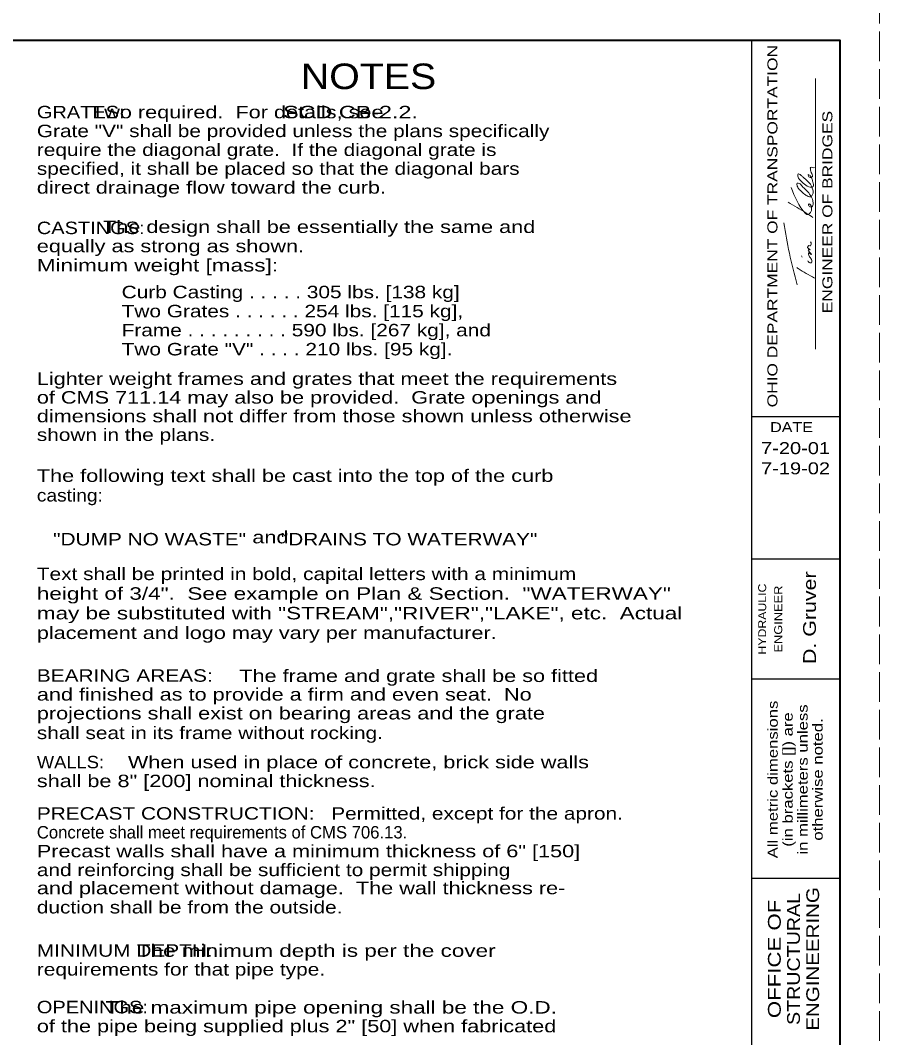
# Model space of a CAD drawing. Extents: x 1352.5 to 1386.5, y 735.9 to 779.9.
# Drawn here: x 1375.75 to 1386.51, y 744.93 to 757.67 of the extents above; entities that cross this region are included whole.
import ezdxf
from ezdxf.enums import TextEntityAlignment as Align

# ---------------------------------------------------------------- set-up
doc = ezdxf.new("R2010")
doc.units = 0
doc.header["$LTSCALE"] = 0.062
doc.linetypes.add('LONG_DASHED', pattern=[7.5, 6, -1.5])
doc.layers.add('1', color=7, linetype='Continuous', lineweight=13)

msp = doc.modelspace()

# ---------------------------------------------------------------- linework, layer by layer
at = {"layer": '1', "lineweight": 25}
for p, q in [((1354.513, 757.41967), (1386.013, 757.41967)), ((1384.913, 736.41967), (1384.913, 757.41967)), ((1386.013, 757.41967), (1386.013, 736.41967)), ((1386.013, 752.70383), (1384.913, 752.70383)), ((1386.013, 750.91967), (1384.913, 750.91967)), ((1386.013, 749.41967), (1384.913, 749.41967)), ((1386.013, 746.91967), (1384.913, 746.91967))]:
    msp.add_line(p, q, dxfattribs=at)
at = {"layer": '1'}
for p, q in [((1385.71175, 753.55067), (1385.71175, 756.94075)), ((1385.54425, 754.70158), (1385.53408, 754.72083))]:
    msp.add_line(p, q, dxfattribs=at)
at = {"layer": '1', "linetype": 'LONG_DASHED'}
msp.add_lwpolyline([(1352.513, 735.91967), (1386.513, 735.91967), (1386.513, 757.91967), (1352.513, 757.91967)], close=True, dxfattribs=at)
at = {"layer": '1', "lineweight": 40}
msp.add_lwpolyline([(1354.513, 757.41967), (1386.013, 757.41967), (1386.013, 736.41967), (1354.513, 736.41967)], close=True, dxfattribs=at)
msp.add_lwpolyline([(1354.513, 757.41967), (1386.013, 757.41967), (1386.013, 736.41967), (1354.513, 736.41967)], close=True, dxfattribs=at)
at = {"layer": '1'}
for points in [[(1385.40483, 755.57667), (1385.588, 755.24833), (1385.60317, 755.23775), (1385.61333, 755.23775), (1385.64525, 755.26142), (1385.66033, 755.29558), (1385.65533, 755.34683), (1385.63842, 755.36867), (1385.62492, 755.36867), (1385.62317, 755.35567), (1385.63333, 755.3405), (1385.64683, 755.33208), (1385.66192, 755.33208), (1385.67708, 755.35367), (1385.6805, 755.373), (1385.67025, 755.42833), (1385.588, 755.54875), (1385.5425, 755.59342), (1385.50558, 755.628), (1385.48042, 755.63017), (1385.48217, 755.59158), (1385.50733, 755.55283), (1385.57458, 755.4905), (1385.61667, 755.46508), (1385.65033, 755.46058), (1385.67367, 755.48658), (1385.6805, 755.52075), (1385.67542, 755.5465), (1385.64525, 755.61967), (1385.615, 755.65167), (1385.55442, 755.70508), (1385.52575, 755.73092), (1385.49225, 755.74617), (1385.48883, 755.71817), (1385.49892, 755.69233), (1385.55608, 755.63242), (1385.62675, 755.58517), (1385.67875, 755.5875), (1385.67708, 755.64517), (1385.66525, 755.68808), (1385.65192, 755.71383), (1385.64175, 755.72458), (1385.61833, 755.73958), (1385.62008, 755.7225), (1385.65533, 755.701), (1385.67025, 755.71175), (1385.65717, 755.76542), (1385.64858, 755.79333), (1385.64525, 755.806), (1385.64525, 755.81883), (1385.64525, 755.8275), (1385.67025, 755.82533), (1385.69567, 755.82533)], [(1385.366, 755.39442), (1385.58975, 755.25692), (1385.67542, 755.20125)], [(1385.48225, 754.35742), (1385.38358, 754.75267), (1385.31233, 755.135)], [(1385.61333, 754.65633), (1385.62158, 754.64567), (1385.65875, 754.63275), (1385.6635, 754.66517), (1385.63842, 754.70158), (1385.62317, 754.73783), (1385.62317, 754.75708), (1385.63842, 754.75083), (1385.64858, 754.74), (1385.65875, 754.73567), (1385.63508, 754.76783), (1385.62317, 754.78283), (1385.62008, 754.80017), (1385.6435, 754.79358), (1385.63508, 754.80225), (1385.60992, 754.83008), (1385.62008, 754.84525), (1385.63683, 754.84725), (1385.64525, 754.84525), (1385.65533, 754.86658), (1385.64858, 754.8945)], [(1385.69742, 754.44183), (1385.49225, 754.56183), (1385.47667, 754.57225)]]:
    msp.add_spline(points, degree=3, dxfattribs=at)

# ---------------------------------------------------------------- texts
for s, height, width, p in [('OHIO DEPARTMENT OF TRANSPORTATION', 0.125, 1.3, (1385.23292, 755.09192)), ('ENGINEER OF BRIDGES', 0.125, 1.3, (1385.92125, 755.26871)), ('D. Gruver', 0.16, 1.25, (1385.715, 750.18792)), ('HYDRAULIC', 0.1, 1.15, (1385.09208, 750.17075)), ('ENGINEER', 0.1, 1.2, (1385.293, 750.17079)), ('All metric dimensions', 0.125, 1.25, (1385.23683, 748.16175)), ('in millimeters unless', 0.125, 1.25, (1385.61183, 748.16179)), ('(in brackets []) are', 0.125, 1.25, (1385.42433, 748.16175)), ('otherwise noted.', 0.125, 1.25, (1385.79933, 748.16175)), ('ENGINEERING', 0.16, 1.2, (1385.75475, 745.91421)), ('OFFICE OF', 0.16, 1.3, (1385.27475, 745.91413)), ('STRUCTURAL', 0.16, 1.15, (1385.51475, 745.91413))]:
    msp.add_text(s, height=height, rotation=90, dxfattribs=dict(at, width=width)).set_placement(p, align=Align.CENTER)
for s, height, width, p in [('NOTES', 0.32, 1.15, (1379.26558, 756.80883)), ('GRATES:', 0.156, 1.2, (1375.96008, 756.44283)), ('         Two required.  For details, see', 0.156, 1.3, (1375.96008, 756.44283)), ('                                      SCD CB-2.2.', 0.156, 1.4, (1375.96008, 756.44283)), ('Grate "V" shall be provided unless the plans specifically', 0.156, 1.25, (1375.96008, 756.20683)), ('require the diagonal grate.  If the diagonal grate is', 0.156, 1.25, (1375.96008, 755.97083)), ('specified, it shall be placed so that the diagonal bars', 0.156, 1.25, (1375.96008, 755.73483)), ('direct drainage flow toward the curb.', 0.156, 1.3, (1375.96008, 755.49883)), ('CASTINGS:', 0.156, 1.2, (1375.96008, 754.99233)), ('           The design shall be essentially the same and', 0.156, 1.3, (1375.96008, 755.00633)), ('equally as strong as shown.', 0.156, 1.3, (1375.96008, 754.76533)), ('Minimum weight [mass]:', 0.156, 1.35, (1375.96008, 754.52433)), ('Curb Casting . . . . . 305 lbs. [138 kg]', 0.156, 1.25, (1377.02208, 754.18908)), ('Two Grates . . . . . . 254 lbs. [115 kg],', 0.156, 1.25, (1377.02208, 753.9505)), ('Frame . . . . . . . . . 590 lbs. [267 kg], and', 0.156, 1.25, (1377.02208, 753.71192)), ('Two Grate "V" . . . . 210 lbs. [95 kg].', 0.156, 1.25, (1377.02208, 753.47333)), ('Lighter weight frames and grates that meet the requirements ', 0.156, 1.3, (1375.96008, 753.10367)), ('of CMS 711.14 may also be provided.  Grate openings and', 0.156, 1.3, (1375.96008, 752.86967)), ('dimensions shall not differ from those shown unless otherwise ', 0.156, 1.3, (1375.96008, 752.63567)), ('shown in the plans.', 0.156, 1.25, (1375.96008, 752.40167)), ('The following text shall be cast into the top of the curb ', 0.156, 1.3, (1375.96008, 751.88908)), ('casting:', 0.156, 1.15, (1375.96008, 751.64308)), ('   "DUMP NO WASTE"      "DRAINS TO WATERWAY"', 0.156, 1.25, (1375.94658, 751.09342)), (' and', 0.156, 1.3, (1378.58333, 751.11917)), ('Text shall be printed in bold, capital letters with a minimum', 0.156, 1.25, (1375.96008, 750.65908)), ('height of 3/4".  See example on Plan & Section.  "WATERWAY" ', 0.156, 1.35, (1375.96008, 750.41308)), ('may be substituted with "STREAM","RIVER","LAKE", etc.  Actual ', 0.156, 1.35, (1375.96008, 750.16708)), ('placement and logo may vary per manufacturer.', 0.156, 1.3, (1375.96008, 749.92108)), ('BEARING AREAS:', 0.156, 1.25, (1375.96008, 749.38583)), ('The frame and grate shall be so fitted', 0.156, 1.3, (1378.49483, 749.38275)), ('and finished as to provide a firm and even seat.  No', 0.156, 1.3, (1375.96008, 749.14983)), ('projections shall exist on bearing areas and the grate', 0.156, 1.3, (1375.96008, 748.91383)), ('shall seat in its frame without rocking.', 0.156, 1.25, (1375.96008, 748.66783)), ('WALLS:', 0.156, 1.1, (1375.96008, 748.30167)), ('When used in place of concrete, brick side walls', 0.156, 1.3, (1377.10008, 748.30167)), ('shall be 8" [200] nominal thickness.', 0.156, 1.3, (1375.96008, 748.06567)), ('PRECAST CONSTRUCTION:', 0.156, 1.25, (1375.96008, 747.659)), ('Permitted, except for the apron.', 0.156, 1.25, (1379.64575, 747.659)), ('Precast walls shall have a minimum thickness of 6" [150]', 0.156, 1.3, (1375.96008, 747.187)), ('and reinforcing shall be sufficient to permit shipping', 0.156, 1.25, (1375.96008, 746.951)), ('and placement without damage.  The wall thickness re-', 0.156, 1.3, (1375.96008, 746.72483)), ('duction shall be from the outside.', 0.156, 1.25, (1375.96008, 746.48383)), ('MINIMUM DEPTH:', 0.156, 1.25, (1375.96008, 745.94183)), ('                The minimum depth is per the cover', 0.156, 1.35, (1375.96008, 745.9405)), ('requirements for that pipe type.', 0.156, 1.25, (1375.96008, 745.70583)), ('OPENINGS:', 0.156, 1.2, (1375.96008, 745.23383)), ('           The maximum pipe opening shall be the O.D.', 0.156, 1.35, (1375.96008, 745.22983)), ('of the pipe being supplied plus 2" [50] when fabricated', 0.156, 1.3, (1375.96008, 744.99517))]:
    msp.add_text(s, height=height, dxfattribs=dict(at, width=width)).set_placement(p)
for s, height, width, p in [('DATE', 0.125, 1.2, (1385.40971, 752.51242)), ('7-20-01', 0.15, 1.25, (1385.46004, 752.23692)), ('7-19-02', 0.15, 1.25, (1385.46004, 751.98383))]:
    msp.add_text(s, height=height, dxfattribs=dict(at, width=width)).set_placement(p, align=Align.CENTER)
msp.add_text('Concrete shall meet requirements of CMS 706.13.', height=0.156, dxfattribs=at).set_placement((1375.96008, 747.423))

doc.saveas('drawing.dxf')
